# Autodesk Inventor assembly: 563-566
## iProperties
Author: Administrator
Shininess: 64.0
Angle Display Precision: 2
Document Length Units: 11272
Document Angle Units: 11286
Document Time Units: 11279
Document Mass Units: 11290
Document Length Units Precision: 3
Document Angle Units Precision: 2
Compacted: True
PropertySet Name: _Private Model Information
Created: 2002-03
Part Number: 563-566
Document SubType Name: Assembly
Designer: Administrator
Control State: 0
Master: False
Checked Out: False
PropertySet Name: Design Tracking Control
Density: 0.0
Volumn: 0.0
Area: 0.0
PropertySet Name: Model Information
